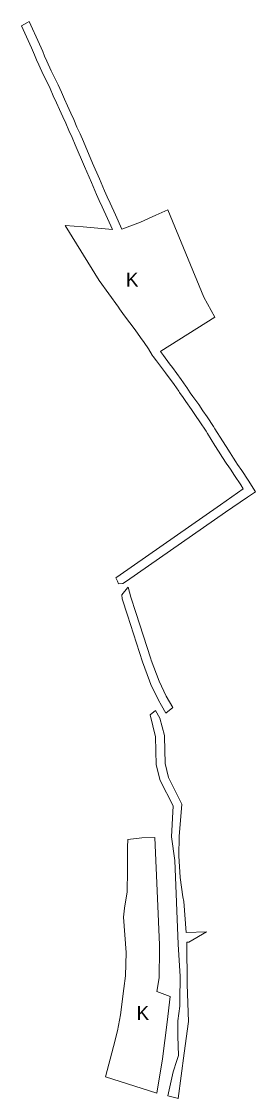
# Model space of a CAD drawing. Extents: x -650276 to -642489, y -1074311 to -1066658.
# Drawn here: x -649558 to -649159, y -1068954 to -1067116 of the extents above; entities that cross this region are included whole.
import ezdxf

# ---------------------------------------------------------------- set-up
doc = ezdxf.new("R2010")
doc.units = 0
doc.header["$LTSCALE"] = 9.6
doc.layers.add('47', color=7, linetype='Continuous', lineweight=13)
doc.layers.add('48', color=7, linetype='Continuous', lineweight=35)

msp = doc.modelspace()

# ---------------------------------------------------------------- linework, layer by layer
at = {"layer": '47'}
for points in [[(-649545.203, -1067115.647), (-649549.7, -1067118.05), (-649558.469, -1067122.73), (-649541.537, -1067160.722), (-649536.075, -1067172.622), (-649532.831, -1067180.855), (-649529.013, -1067189.389), (-649521.663, -1067206.124), (-649514.869, -1067218.957), (-649509.44, -1067230.141), (-649504.224, -1067242.225), (-649498.572, -1067254.427), (-649493.526, -1067265.611), (-649487.812, -1067278.312), (-649482.963, -1067288.934), (-649477.677, -1067301.655), (-649472.327, -1067313.644), (-649466.703, -1067326.24), (-649451.059, -1067363.074), (-649439.265, -1067390.397), (-649430.531, -1067410.689), (-649425.804, -1067421.21), (-649421.071, -1067431.944), (-649411.913, -1067451.746), (-649403.34, -1067470.579)], [(-649387.17, -1067469.894), (-649398.28, -1067445.49), (-649407.4, -1067425.77), (-649412.1, -1067415.11), (-649416.8, -1067404.65), (-649425.49, -1067384.46), (-649437.27, -1067357.17), (-649452.95, -1067320.25), (-649458.63, -1067307.53), (-649463.9, -1067295.72), (-649469.21, -1067282.94), (-649474.15, -1067272.12), (-649479.85, -1067259.45), (-649484.93, -1067248.19), (-649490.53, -1067236.1), (-649495.8, -1067223.89), (-649501.49, -1067212.17), (-649508.15, -1067199.59), (-649515.3, -1067183.31), (-649519, -1067175.04), (-649522.27, -1067166.74), (-649527.87, -1067154.54), (-649545.203, -1067115.647)], [(-649321.3, -1067679), (-649320.47, -1067678.44), (-649228.52, -1067620.294), (-649247.518, -1067586.255), (-649308.75, -1067437.11), (-649329.068, -1067446.175), (-649355.44, -1067457.94), (-649387.17, -1067469.894)], [(-649403.34, -1067470.579), (-649453.39, -1067466.13), (-649484.28, -1067463.88), (-649425.69, -1067557.7), (-649393.23, -1067603.28), (-649391.04, -1067606.27), (-649382.53, -1067618.33), (-649364.69, -1067641.98), (-649355.46, -1067654.85), (-649349.12, -1067663.84), (-649341.81, -1067674.33), (-649335.26, -1067685.21), (-649333.74, -1067687.4)], [(-649333.74, -1067687.4), (-649328.34, -1067694.79), (-649317.99, -1067708.85), (-649312.91, -1067715.45), (-649298.02, -1067735.58), (-649290.15, -1067746.92), (-649288.63, -1067748.97), (-649282.85, -1067757.79), (-649278.14, -1067764.31), (-649268.46, -1067777.97), (-649261.48, -1067788.47), (-649253.98, -1067799.2), (-649243.37, -1067815.17), (-649241.28, -1067818.7), (-649228.27, -1067839.26), (-649222.11, -1067849.12), (-649215.32, -1067859.99), (-649209.39, -1067869.34), (-649204.87, -1067875.85), (-649202.02, -1067880.07), (-649194.77, -1067890.67), (-649184, -1067906.88), (-649179.96, -1067913.35), (-649219.088, -1067940.964), (-649395.729, -1068064.23), (-649397.466, -1068065.442), (-649394.83, -1068071.05), (-649392.88, -1068075.9), (-649385.41, -1068075.32), (-649379.295, -1068071.053), (-649210.54, -1067953.29), (-649172.99, -1067927.41), (-649159.179, -1067918.309), (-649171.389, -1067898.756), (-649182.332, -1067882.285), (-649189.614, -1067871.638), (-649192.493, -1067867.375), (-649196.89, -1067861.042), (-649202.625, -1067852), (-649209.388, -1067841.173), (-649215.571, -1067831.276), (-649228.486, -1067810.867), (-649230.661, -1067807.193), (-649241.584, -1067790.752), (-649249.085, -1067780.02), (-649256.092, -1067769.48), (-649265.941, -1067755.582), (-649270.491, -1067749.283), (-649276.322, -1067740.385), (-649277.961, -1067738.175), (-649285.826, -1067726.842), (-649300.936, -1067706.414), (-649306.005, -1067699.828), (-649316.244, -1067685.919), (-649321.3, -1067679)], [(-649376.467, -1068081.552), (-649377.77, -1068082.44), (-649387.46, -1068094.51), (-649386.74, -1068101.31), (-649377.81, -1068129), (-649352.11, -1068208.65)], [(-649352.11, -1068208.65), (-649339.94, -1068241.13), (-649337.52, -1068247.59), (-649324.66, -1068274.3), (-649319.551, -1068283.382), (-649312.087, -1068296.653), (-649300.305, -1068287.002), (-649311.352, -1068267.362), (-649323.711, -1068241.693), (-649337.178, -1068205.751), (-649337.942, -1068203.713), (-649363.534, -1068124.395), (-649371.987, -1068098.185), (-649376.467, -1068081.552)], [(-649330.038, -1068291.976), (-649339.046, -1068299.359), (-649329.644, -1068336.779), (-649328.386, -1068384.468), (-649321.727, -1068411.472), (-649299.894, -1068454.728), (-649302.681, -1068507.363)], [(-649289.24, -1068506.8), (-649284.59, -1068451.76), (-649307.57, -1068406.23), (-649313.42, -1068382.51), (-649314.27, -1068336.41), (-649314.693, -1068334.727), (-649322.18, -1068304.93), (-649330.038, -1068291.976)], [(-649327.679, -1068945.222), (-649318.13, -1068886.42), (-649314.07, -1068855.33), (-649310.01, -1068824.2), (-649304.66, -1068780.33), (-649327.8, -1068771.82), (-649323.68, -1068748.06), (-649323.1, -1068699.28), (-649323.02, -1068692.1), (-649326.53, -1068612.89), (-649331.151, -1068508.557), (-649353.17, -1068509.48), (-649376.77, -1068511.96), (-649377.52, -1068525.1), (-649377.56, -1068564.89), (-649378.08, -1068601.24), (-649382.46, -1068629.34), (-649384.31, -1068644.92), (-649379.97, -1068704.98), (-649381.06, -1068744.69), (-649383.78, -1068766.6)], [(-649302.681, -1068507.363), (-649296.55, -1068548.09), (-649290.93, -1068690.93), (-649287.98, -1068745.74), (-649288.19, -1068786.39), (-649288.24, -1068796.6), (-649291.64, -1068821.88), (-649291.87, -1068848.02), (-649290.28, -1068880.82), (-649293.33, -1068889.65), (-649299.91, -1068908.66), (-649308.65, -1068950), (-649293.04, -1068953.81), (-649291.32, -1068954.23), (-649281.01, -1068876.69), (-649273.66, -1068822.58), (-649275.96, -1068759.73), (-649276.43, -1068688.29), (-649276.474, -1068687.673), (-649272.755, -1068687.618)], [(-649277.655, -1068670.983), (-649281.4, -1068618.05), (-649282.97, -1068610.04), (-649287.71, -1068577.14), (-649289.74, -1068540.2), (-649289.24, -1068506.8)], [(-649272.755, -1068687.618), (-649272.69, -1068687.58), (-649242.507, -1068669.925), (-649277.655, -1068670.983)], [(-649383.78, -1068766.6), (-649389.34, -1068811.43), (-649394.48, -1068838.89), (-649401.31, -1068865.78), (-649415.09, -1068917.1), (-649327.679, -1068945.222)]]:
    msp.add_lwpolyline(points, dxfattribs=at)

# ---------------------------------------------------------------- texts
at = {"layer": '48'}
for p in [(-649380.314, -1067568.167), (-649380.314, -1067568.167), (-649362.16, -1068820.233), (-649362.16, -1068820.233)]:
    msp.add_text('K', height=24, dxfattribs=at).set_placement(p)

doc.saveas('drawing.dxf')
